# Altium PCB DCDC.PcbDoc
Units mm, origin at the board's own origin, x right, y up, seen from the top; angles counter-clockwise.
Board outline 16.5 x 19 mm, 2 copper layers (Top Layer, Bottom Layer); 11 components, 7 nets, 28 pads, 10 vias.
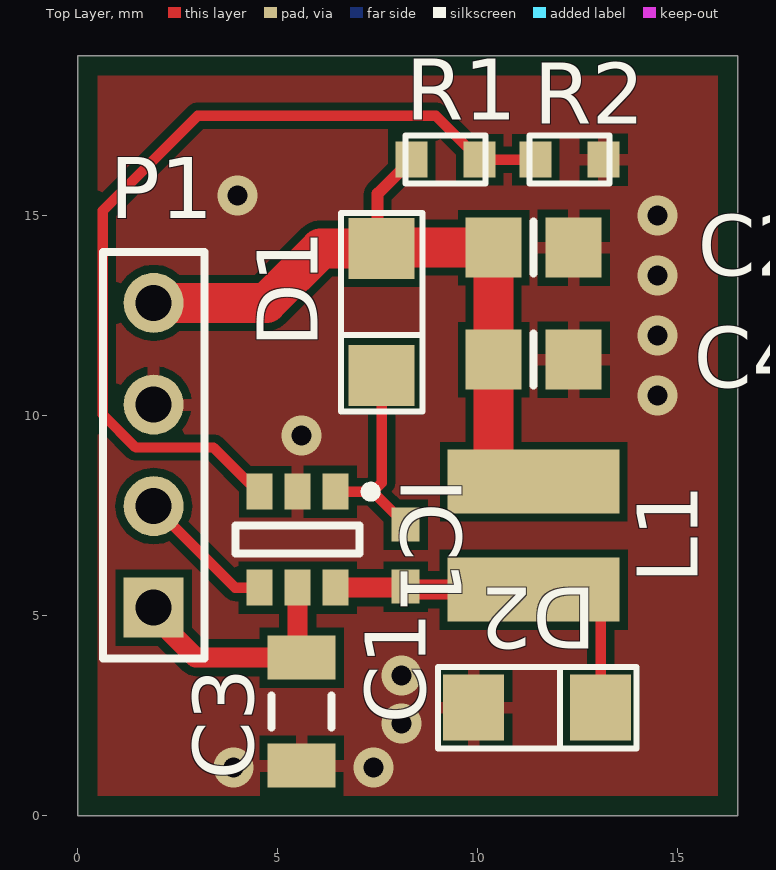
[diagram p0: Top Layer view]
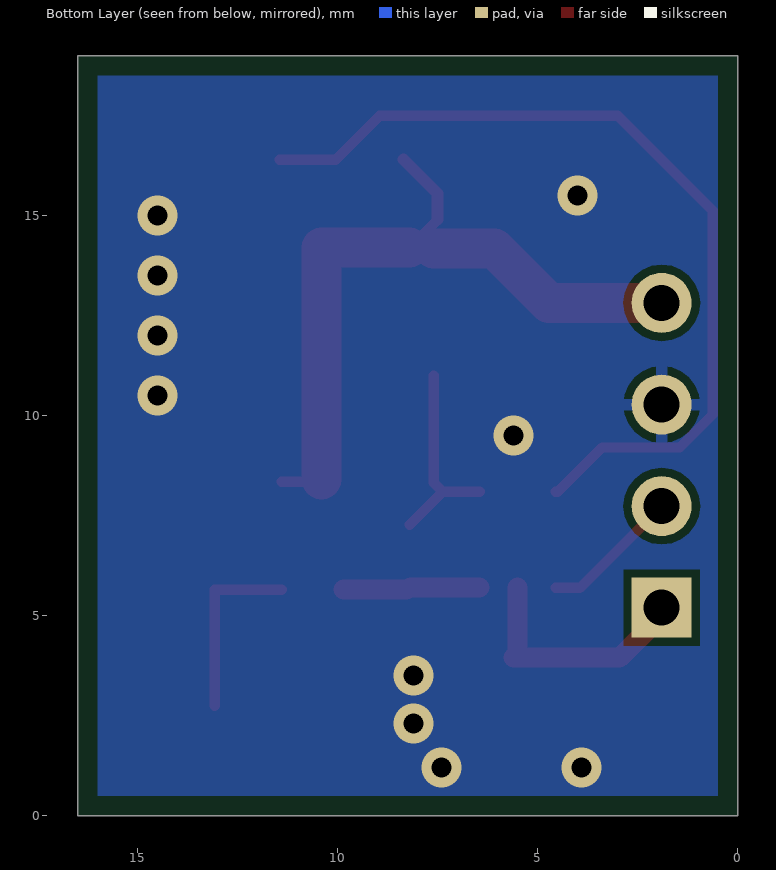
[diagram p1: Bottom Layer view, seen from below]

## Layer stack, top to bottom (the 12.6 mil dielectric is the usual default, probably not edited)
Top Layer: signal copper 0.0356
Dielectric: dielectric 0.32, FR-4, Dk 4.8
Bottom Layer: signal copper 0.0356

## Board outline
0,19 0,0 16.5,0 16.5,19

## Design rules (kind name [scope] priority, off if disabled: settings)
AssemblyTestPointUsage [All] p1 off:
Clearance [All] p1: gap=0.2
DiffPairsRouting [All] p1 off: maxlimit=0.254 minlimit=0.254 mostfreqgap=0.254 maxuncoupledlength=12.7
FabricationTestPointUsage [All] p1 off: valid=0 allowmultiple=FALSE
FabricationTestpoint [All] p1 off: side=3 testpointundercomponent=TRUE minsize=1.016 maxsize=2.54 preferedsize=1.524 minholesize=0 maxholesize=1.016 preferedholesize=0.813 testpointgrid=0.025 allowsidetop=TRUE allowsidebottom=TRUE usegrid=TRUE gridtolerance=0
MinimumSolderMaskSliver [All] p1 off: minsoldermaskwidth=0.254
PlaneClearance [All] p1: clearance=0.2
PlaneConnect PlaneConnect_1 [IsVia] p1: planeconnectstyle=Direct reliefexpansion=0.508 reliefentries=4 reliefconductorwidth=0.254 reliefairgap=0.254
PlaneConnect [isPad] p2: planeconnectstyle=Relief reliefexpansion=0.508 reliefentries=4 reliefconductorwidth=0.254 reliefairgap=0.2
PolygonConnect [isVia] p1: connectstyle=Direct reliefconductorwidth=0.254 reliefentries=4 polygonreliefangle="90 Angle"
PolygonConnect PolygonConnect_1 [All vs isPad] p2: connectstyle=Relief reliefconductorwidth=0.3 reliefentries=4 polygonreliefangle="90 Angle"
RoomDefinition U_DCDC [InComponentClass('U_DCDC')] p1 off: confinementstyle=ConfineIn formatcopy=TRUE lockcomponents=FALSE outline -148.5,-36 -97.7,-36 -97.7,-10.6 -148.5,-10.6
RoomDefinition TOP [InComponentClass('TOP')] p2 off: confinementstyle=ConfineIn formatcopy=TRUE lockcomponents=FALSE outline -148.5,-36 -97.7,-36 -97.7,-10.6 -148.5,-10.6
RoutingVias [All] p1: holewidth=0.5 width=1 viastyle="Through Hole" minholewidth=0.5 minwidth=1 maxholewidth=0.5 maxwidth=1
SilkToSilkClearance [All] p1 off: silktosilkclearance=0.254
SilkscreenOverComponentPads [All] p1 off: minsilkscreentomaskgap=0.254
SolderMaskExpansion [All] p1: expansion=0.102
Width [All] p1: maxlimit=3 minlimit=0.254 preferedwidth=0.254
19 further rules are at their usual default settings.

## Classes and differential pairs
component class U_DCDC: C1 C2 C3 C4 D1 D2 IC1 L1 R1 R2
component class TOP: P1

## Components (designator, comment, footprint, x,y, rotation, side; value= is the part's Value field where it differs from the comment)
C1 "C02X60Y0A1" "SMD 0603" 8.2,6.5 r90 top
C2 "C02X60Y0A1" 6-0805_M 11.4,14.2 r0 top
C3 "C02X60Y0A1" C1206 5.6,2.6 r90 top
C4 "C02X60Y0A1" 6-0805_M 11.4,11.4 r0 top
D1 "D02X125Y0A0" D02X125Y0A0 7.6,11 r90 top
D2 "D02X125Y0A0" D02X125Y0A0 13.075,2.7 r180 top
IC1 "mcp16301" SOT23-6_L 5.5,6.9 r270 top
L1 "15.0 µH" "WE-TPC 3816, S" 11.4,7 r90 top
P1 "Header 4" HDR1X4 1.9,5.2 r90 top
R1 "R02X60Y0A0" R02X60Y0A0 9.2,16.4 r180 top
R2 "R02X60Y0A0" R02X60Y0A0 12.3,16.4 r180 top

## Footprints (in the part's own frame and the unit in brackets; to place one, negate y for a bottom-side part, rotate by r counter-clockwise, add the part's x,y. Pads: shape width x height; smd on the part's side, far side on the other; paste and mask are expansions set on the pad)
6-0805_M [mm] "Chip Resistor, Body 2.0x1.2mm, IPC Low Density"
  rect 1.4x1.5 smd: 1(-1,0) 2(1,0)
  silkscreen extent 0,-0.65 0,0.65, body extent -1.07,-0.7 1.07,0.7, height 0.7
C1206 [mm] "Chip Capacitor, Body 3.2x1.6mm, IPC High Density"
  rect 1.1x1.7 smd: 1(-1.35,0) 2(1.35,0)
  silkscreen extent -0.4,-0.75 0.4,0.75, body extent -1.7,-0.9 1.7,0.9, height 1.3
D02X125Y0A0 [mil]
  rect 60x65 smd: A(125,0) K(0,0)
  silkscreen extent -35,-40 160,40
HDR1X4 [mm] "Connector; Header; 4 Position"
  rect 1.5x1.5 hole 0.9: 1(0,0)
  round 1.5 hole 0.9: 2(2.54,0) 3(5.08,0) 4(7.62,0)
  silkscreen extent -1.27,-1.27 8.89,1.27
R02X60Y0A0 [mm]
  rect 0.8x0.9 smd: 1(-0.85,0) 2(0.85,0)
  silkscreen extent -1,-0.6 1,0.6
"SMD 0603" [mm] "Chip Inductor, 2-Leads, Body 1,6x0,8mm"
  rect 0.85x0.7 smd: 1(-0.775,0) 2(0.775,0)
  body extent -0.8,-0.4 0.8,0.4, height 0.79
SOT23-6_L [mm] "SOT23, 6-Leads, Body 2.9x1.6mm, Pitch 0.95mm, Lead Span 2.7mm, IPC High Density"
  rect 0.9x0.65 smd: 1(-1.2,0.95) 2(-1.2,0) 3(-1.2,-0.95) 4(1.2,-0.95) 5(1.2,0) 6(1.2,0.95)
  silkscreen extent -1.32,-1.55 0.35,1.95, body extent -0.9,-1.55 0.9,1.55, height 1.45
"WE-TPC 3816, S" [mm] "SMD Inductor, 2-Leads, Body 3,8x3,8mm"
  rect 1.6x4.3 smd: 1(-1.35,0) 2(1.35,0)
  body extent -1.9,-1.9 1.9,1.9, height 1.64

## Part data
C1 C2 C3 C4: library part C1210/10U/16V/X7R
D1 D2: library part D_LL4148/MMELF
L1: library part "WE-TPC 3816, S, 744031150", "SMD Shielded Tiny Power Inductor WE-TPC, L=15.0 µH"
P1: "Header, 4-Pin"
R1 R2: library part R06/1M

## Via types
v1: diameter 1, hole 0.5, Top Layer to Bottom Layer, 10 vias

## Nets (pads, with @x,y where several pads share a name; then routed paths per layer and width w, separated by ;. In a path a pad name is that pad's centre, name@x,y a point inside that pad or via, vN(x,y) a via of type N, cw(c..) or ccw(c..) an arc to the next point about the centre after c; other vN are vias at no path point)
ENA: IC1.4 P1.2 | length 3.5
  Top Layer w0.254: P1.2 3.94,5.7 IC1.4
GND: C2.2 C3.1 C4.2 D2.A IC1.2 P1.3 R2.1
  other v1: 3.9,1.2 7.4,1.2 8.1,2.3 8.1,3.5 5.6,9.5 14.5,10.5 14.5,12 14.5,13.5 14.5,15 4,15.5
NetC1_1: C1.1 D2.K IC1.6 L1.1 | length 7.9
  Top Layer w0.254: L1.1 13.075,5.65 D2.K@13.075,2.75
  Top Layer w0.5: IC1.6 C1.1@8.175,5.7 ; C1.1@8.275,5.65 L1.1@9.85,5.65
NetC1_2: C1.2 D1.K IC1.1 | length 5.1
  Top Layer w0.254: IC1.1 7.375,8.1 ; D1.K 7.6,8.325 7.375,8.1 ; C1.2 7.375,8.1
NetIC1_3: IC1.3 R1.1 R2.2 | length 22.1
  Top Layer w0.254: IC1.3 4.5,8.1 3.397,9.203 1.454,9.203 0.625,10.032 0.625,15.125 3,17.5 8.95,17.5 R1.1 R2.2
VIN: C3.2 IC1.5 P1.1 | length 6.1
  Top Layer w0.254: P1.1@1.9,5 P1.1
  Top Layer w0.5: P1.1@1.9,5 2.95,3.95 C3.2 5.5,4.05 IC1.5
VOUT: C2.1 C4.1 D1.A L1.2 P1.4 R1.2 | length 18.8
  Top Layer w0.254: D1.A@7.5,14.9 D1.A@8.2,14.2 ; D1.A 7.625,14.2 D1.A@8.2,14.2 ; D1.A@8.175,14.175 D1.A@8.2,14.2 ; L1.2@10.4,8.4 10.45,8.35 L1.2
  Top Layer w0.3: D1.A@7.5,14.9 7.5,15.55 R1.2
  Top Layer w1: P1.4 4.72,12.82 6.075,14.175 D1.A ; D1.A@8.2,14.2 C2.1 C4.1 L1.2@10.4,8.4

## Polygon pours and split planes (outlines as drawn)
GND on Bottom Layer "Top Layer-No Net" (solid, pour order 4): 0.5,18.5 0.5,0.5 16,0.5 16,18.5 0.5,18.5
GND on Top Layer "Top Layer-No Net" (solid, pour order 2): 0.5,18 0.5,0.5 16,0.5 16,18.5 0.5,18.5 0.5,18

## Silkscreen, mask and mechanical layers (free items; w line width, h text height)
Mechanical 1:
  the board outline again, w0.2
